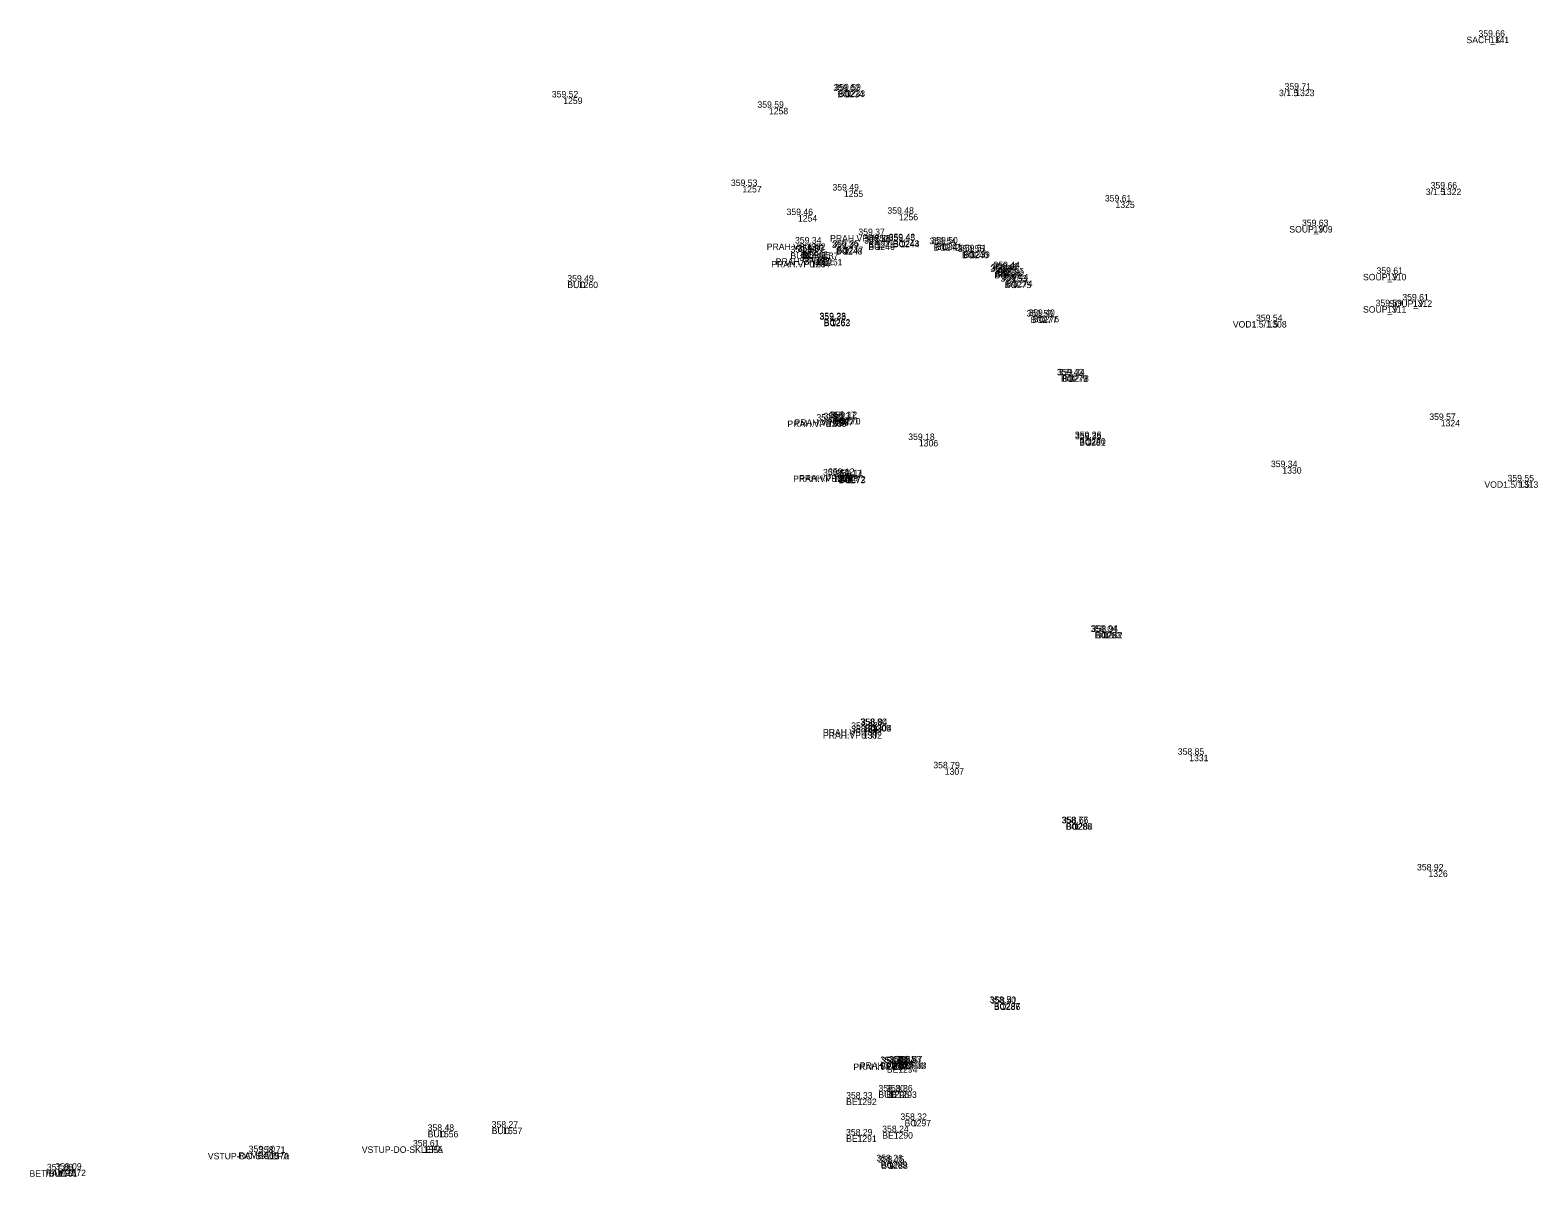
# Model space of a CAD drawing. Extents: x -590413 to -590216, y -1129419 to -1129249.
# Drawn here: x -590376.56 to -590353.25, y -1129285.39 to -1129267.65 of the extents above; entities that cross this region are included whole.
import ezdxf

# ---------------------------------------------------------------- set-up
doc = ezdxf.new("R2010")
doc.units = 0
for name, color, linetype in [('Vrstva B24', 7, 'Continuous'), ('Vrstva B58', 7, 'Continuous'), ('Vrstva B59', 7, 'Continuous'), ('Vrstva B60', 7, 'Continuous')]:
    doc.layers.add(name, color=color, linetype=linetype)

msp = doc.modelspace()

# ---------------------------------------------------------------- linework, layer by layer
at = {"layer": 'Vrstva B60'}
for p, q in [((-590353.99, -1129267.75), (-590353.99, -1129267.75)), ((-590363.97, -1129268.59), (-590363.97, -1129268.59)), ((-590363.95, -1129268.58), (-590363.95, -1129268.58)), ((-590357, -1129268.57), (-590357, -1129268.57)), ((-590368.32, -1129268.69), (-590368.32, -1129268.69)), ((-590365.14, -1129268.85), (-590365.14, -1129268.85)), ((-590365.55, -1129270.06), (-590365.55, -1129270.06)), ((-590363.98, -1129270.13), (-590363.98, -1129270.13)), ((-590359.78, -1129270.3), (-590359.78, -1129270.3)), ((-590354.73, -1129270.1), (-590354.73, -1129270.1)), ((-590364.69, -1129270.51), (-590364.69, -1129270.51)), ((-590363.13, -1129270.49), (-590363.13, -1129270.49)), ((-590356.72, -1129270.68), (-590356.72, -1129270.68)), ((-590364.56, -1129270.95), (-590364.56, -1129270.95)), ((-590363.98, -1129271), (-590363.98, -1129271)), ((-590363.58, -1129270.82), (-590363.58, -1129270.82)), ((-590363.49, -1129270.92), (-590363.49, -1129270.92)), ((-590363.49, -1129270.95), (-590363.49, -1129270.95)), ((-590363.11, -1129270.9), (-590363.11, -1129270.9)), ((-590363.11, -1129270.91), (-590363.11, -1129270.91)), ((-590362.48, -1129270.96), (-590362.48, -1129270.96)), ((-590362.45, -1129270.95), (-590362.45, -1129270.95)), ((-590364.63, -1129271.09), (-590364.63, -1129271.09)), ((-590364.52, -1129271.07), (-590364.52, -1129271.07)), ((-590364.52, -1129271.08), (-590364.52, -1129271.08)), ((-590364.49, -1129271.22), (-590364.49, -1129271.22)), ((-590364.42, -1129271.18), (-590364.42, -1129271.18)), ((-590364.3, -1129271.19), (-590364.3, -1129271.19)), ((-590363.99, -1129271.02), (-590363.99, -1129271.02)), ((-590362.04, -1129271.08), (-590362.04, -1129271.08)), ((-590362.02, -1129271.07), (-590362.02, -1129271.07)), ((-590361.54, -1129271.39), (-590361.54, -1129271.39)), ((-590361.53, -1129271.37), (-590361.53, -1129271.37)), ((-590361.5, -1129271.35), (-590361.5, -1129271.35)), ((-590361.49, -1129271.33), (-590361.49, -1129271.33)), ((-590355.58, -1129271.42), (-590355.58, -1129271.42)), ((-590368.08, -1129271.54), (-590368.08, -1129271.54)), ((-590361.38, -1129271.54), (-590361.38, -1129271.54)), ((-590361.36, -1129271.52), (-590361.36, -1129271.52)), ((-590355.58, -1129271.92), (-590355.58, -1129271.92)), ((-590355.18, -1129271.83), (-590355.18, -1129271.83)), ((-590364.18, -1129272.12), (-590364.18, -1129272.12)), ((-590364.18, -1129272.13), (-590364.18, -1129272.13)), ((-590360.98, -1129272.08), (-590360.98, -1129272.08)), ((-590360.95, -1129272.07), (-590360.95, -1129272.07)), ((-590357.43, -1129272.15), (-590357.43, -1129272.15)), ((-590360.51, -1129272.99), (-590360.51, -1129272.99)), ((-590360.49, -1129272.99), (-590360.49, -1129272.99)), ((-590364.24, -1129273.69), (-590364.24, -1129273.69)), ((-590364.13, -1129273.67), (-590364.13, -1129273.67)), ((-590364.04, -1129273.65), (-590364.04, -1129273.65)), ((-590364.02, -1129273.65), (-590364.02, -1129273.65)), ((-590354.75, -1129273.68), (-590354.75, -1129273.68)), ((-590362.82, -1129273.99), (-590362.82, -1129273.99)), ((-590360.23, -1129273.96), (-590360.23, -1129273.96)), ((-590360.23, -1129273.98), (-590360.23, -1129273.98)), ((-590357.2, -1129274.41), (-590357.2, -1129274.41)), ((-590364.15, -1129274.54), (-590364.15, -1129274.54)), ((-590364.06, -1129274.53), (-590364.06, -1129274.53)), ((-590363.95, -1129274.56), (-590363.95, -1129274.56)), ((-590363.94, -1129274.55), (-590363.94, -1129274.55)), ((-590353.54, -1129274.63), (-590353.54, -1129274.63)), ((-590359.99, -1129276.96), (-590359.99, -1129276.96)), ((-590359.97, -1129276.96), (-590359.97, -1129276.96)), ((-590363.69, -1129278.46), (-590363.69, -1129278.46)), ((-590363.55, -1129278.4), (-590363.55, -1129278.4)), ((-590363.54, -1129278.4), (-590363.54, -1129278.4)), ((-590363.69, -1129278.51), (-590363.69, -1129278.51)), ((-590358.64, -1129278.86), (-590358.64, -1129278.86)), ((-590362.42, -1129279.07), (-590362.42, -1129279.07)), ((-590360.44, -1129279.92), (-590360.44, -1129279.92)), ((-590360.43, -1129279.92), (-590360.43, -1129279.92)), ((-590354.94, -1129280.65), (-590354.94, -1129280.65)), ((-590361.55, -1129282.7), (-590361.55, -1129282.7)), ((-590361.55, -1129282.71), (-590361.55, -1129282.71)), ((-590363.24, -1129283.63), (-590363.24, -1129283.63)), ((-590363.22, -1129283.64), (-590363.22, -1129283.64)), ((-590363.14, -1129283.68), (-590363.14, -1129283.68)), ((-590363.12, -1129283.62), (-590363.12, -1129283.62)), ((-590363.02, -1129283.62), (-590363.02, -1129283.62)), ((-590363, -1129283.62), (-590363, -1129283.62)), ((-590363.77, -1129284.18), (-590363.77, -1129284.18)), ((-590363.27, -1129284.07), (-590363.27, -1129284.07)), ((-590363.15, -1129284.07), (-590363.15, -1129284.07)), ((-590362.93, -1129284.51), (-590362.93, -1129284.51)), ((-590370.24, -1129284.68), (-590370.24, -1129284.68)), ((-590369.25, -1129284.63), (-590369.25, -1129284.63)), ((-590363.77, -1129284.75), (-590363.77, -1129284.75)), ((-590363.21, -1129284.7), (-590363.21, -1129284.7)), ((-590370.48, -1129284.92), (-590370.48, -1129284.92)), ((-590373.02, -1129285.01), (-590373.02, -1129285.01)), ((-590372.86, -1129285.02), (-590372.86, -1129285.02)), ((-590363.3, -1129285.15), (-590363.3, -1129285.15)), ((-590363.29, -1129285.17), (-590363.29, -1129285.17)), ((-590376.13, -1129285.29), (-590376.13, -1129285.29)), ((-590376, -1129285.28), (-590376, -1129285.28))]:
    msp.add_line(p, q, dxfattribs=at)

# ---------------------------------------------------------------- texts
at = {"layer": 'Vrstva B24'}
for s, p in [('SACH_K', (-590354.352, -1129267.85)), ('BO', (-590364.082, -1129268.69)), ('BO', (-590364.062, -1129268.68)), ('3/1.5', (-590357.251, -1129268.67)), ('3/1.5', (-590354.981, -1129270.2)), ('SOUP_V', (-590357.092, -1129270.78)), ('PRAH.VPUST', (-590365.174, -1129271.05)), ('PRAH.VPUST', (-590364.194, -1129270.92)), ('BO', (-590364.092, -1129271.1)), ('BO', (-590363.602, -1129271.02)), ('BO', (-590363.602, -1129271.05)), ('BO', (-590363.222, -1129271)), ('BO', (-590363.222, -1129271.01)), ('BO', (-590362.592, -1129271.06)), ('BO', (-590362.562, -1129271.05)), ('PRAH.VPUST', (-590365.104, -1129271.32)), ('PRAH.VPUST', (-590365.034, -1129271.28)), ('BUD', (-590364.807, -1129271.19)), ('BO', (-590364.632, -1129271.17)), ('BO', (-590364.632, -1129271.18)), ('BO', (-590364.412, -1129271.29)), ('BO', (-590364.102, -1129271.12)), ('BO', (-590362.152, -1129271.18)), ('BO', (-590362.132, -1129271.17)), ('BO', (-590361.652, -1129271.49)), ('BO', (-590361.642, -1129271.47)), ('BO', (-590361.612, -1129271.45)), ('BO', (-590361.602, -1129271.43)), ('SOUP_V', (-590355.952, -1129271.52)), ('BUD', (-590368.257, -1129271.64)), ('BO', (-590361.492, -1129271.64)), ('BO', (-590361.472, -1129271.62)), ('SOUP_V', (-590355.952, -1129272.02)), ('SOUP_V', (-590355.552, -1129271.93)), ('BO', (-590364.292, -1129272.22)), ('BO', (-590364.292, -1129272.23)), ('BO', (-590361.092, -1129272.18)), ('BO', (-590361.062, -1129272.17)), ('VOD1.5/1.5', (-590357.965, -1129272.25)), ('BO', (-590360.622, -1129273.09)), ('BO', (-590360.602, -1129273.09)), ('PRAH.VPUST', (-590364.854, -1129273.79)), ('PRAH.VPUST', (-590364.744, -1129273.77)), ('BO', (-590364.152, -1129273.75)), ('BO', (-590364.132, -1129273.75)), ('BO', (-590360.342, -1129274.06)), ('BO', (-590360.342, -1129274.08)), ('PRAH.VPUST', (-590364.764, -1129274.64)), ('PRAH.VPUST', (-590364.674, -1129274.63)), ('BO', (-590364.062, -1129274.66)), ('BO', (-590364.052, -1129274.65)), ('VOD1.5/1.5', (-590354.075, -1129274.73)), ('BO', (-590360.102, -1129277.06)), ('BO', (-590360.082, -1129277.06)), ('PRAH.VPUST', (-590364.304, -1129278.56)), ('BO', (-590363.662, -1129278.5)), ('BO', (-590363.652, -1129278.5)), ('PRAH.VPUST', (-590364.304, -1129278.61)), ('BO', (-590360.552, -1129280.02)), ('BO', (-590360.542, -1129280.02)), ('BO', (-590361.662, -1129282.8)), ('BO', (-590361.662, -1129282.81)), ('PRAH.VPUST', (-590363.834, -1129283.74)), ('PRAH.VPUST', (-590363.734, -1129283.72)), ('BET', (-590363.416, -1129283.73)), ('BET', (-590363.316, -1129283.78)), ('BO', (-590363.132, -1129283.72)), ('BO', (-590363.112, -1129283.72)), ('BET', (-590363.946, -1129284.28)), ('BUD', (-590363.447, -1129284.17)), ('BET', (-590363.326, -1129284.17)), ('BO', (-590363.042, -1129284.61)), ('BUD', (-590370.417, -1129284.78)), ('BUD', (-590369.427, -1129284.73)), ('BET', (-590363.946, -1129284.85)), ('BET', (-590363.386, -1129284.8)), ('VSTUP-DO-SKLEPA', (-590371.436, -1129285.02)), ('VSTUP-DO-SKLEPA', (-590373.816, -1129285.12)), ('RAMPA', (-590373.343, -1129285.11)), ('BO', (-590363.412, -1129285.25)), ('BO', (-590363.402, -1129285.27)), ('BET/BUD', (-590376.575, -1129285.39)), ('RAMPA', (-590376.323, -1129285.38))]:
    msp.add_text(s, height=0.1, dxfattribs=at).set_placement(p)
at = {"layer": 'Vrstva B58'}
for s, p in [('359.66', (-590354.166, -1129267.75)), ('359.52', (-590368.497, -1129268.69)), ('359.62', (-590364.146, -1129268.59)), ('359.59', (-590364.127, -1129268.58)), ('359.71', (-590357.165, -1129268.57)), ('359.59', (-590365.317, -1129268.85)), ('359.53', (-590365.727, -1129270.06)), ('359.49', (-590364.157, -1129270.13)), ('359.66', (-590354.906, -1129270.1)), ('359.61', (-590359.944, -1129270.3)), ('359.46', (-590364.867, -1129270.51)), ('359.48', (-590363.307, -1129270.49)), ('359.37', (-590363.756, -1129270.82)), ('359.63', (-590356.896, -1129270.68)), ('359.34', (-590364.806, -1129271.09)), ('359.34', (-590364.736, -1129270.95)), ('359.33', (-590364.696, -1129271.07)), ('359.37', (-590364.696, -1129271.08)), ('359.39', (-590364.166, -1129271.02)), ('359.35', (-590364.156, -1129271)), ('359.40', (-590363.667, -1129270.95)), ('359.38', (-590363.666, -1129270.92)), ('359.43', (-590363.287, -1129270.9)), ('359.45', (-590363.287, -1129270.91)), ('359.54', (-590362.657, -1129270.96)), ('359.50', (-590362.627, -1129270.95)), ('359.55', (-590362.217, -1129271.08)), ('359.51', (-590362.185, -1129271.07)), ('359.35', (-590364.666, -1129271.22)), ('359.35', (-590364.596, -1129271.18)), ('359.37', (-590364.476, -1129271.19)), ('359.44', (-590361.667, -1129271.33)), ('359.49', (-590368.257, -1129271.54)), ('359.54', (-590361.717, -1129271.39)), ('359.47', (-590361.707, -1129271.37)), ('359.47', (-590361.677, -1129271.35)), ('359.53', (-590361.557, -1129271.54)), ('359.44', (-590361.537, -1129271.52)), ('359.61', (-590355.744, -1129271.42)), ('359.59', (-590355.757, -1129271.92)), ('359.61', (-590355.344, -1129271.83)), ('359.28', (-590364.357, -1129272.12)), ('359.33', (-590364.356, -1129272.13)), ('359.50', (-590361.157, -1129272.08)), ('359.40', (-590361.127, -1129272.07)), ('359.54', (-590357.607, -1129272.15)), ('359.43', (-590360.687, -1129272.99)), ('359.34', (-590360.666, -1129272.99)), ('359.13', (-590364.295, -1129273.67)), ('359.17', (-590364.205, -1129273.65)), ('359.12', (-590364.185, -1129273.65)), ('359.12', (-590364.405, -1129273.69)), ('359.57', (-590354.927, -1129273.68)), ('359.18', (-590362.985, -1129273.99)), ('359.26', (-590360.407, -1129273.96)), ('359.35', (-590360.406, -1129273.98)), ('359.11', (-590364.303, -1129274.54)), ('359.12', (-590364.225, -1129274.53)), ('359.17', (-590364.115, -1129274.56)), ('359.11', (-590364.093, -1129274.55)), ('359.34', (-590357.376, -1129274.41)), ('359.55', (-590353.717, -1129274.63)), ('359.04', (-590360.167, -1129276.96)), ('358.94', (-590360.147, -1129276.96)), ('358.87', (-590363.867, -1129278.46)), ('358.88', (-590363.867, -1129278.51)), ('358.90', (-590363.727, -1129278.4)), ('358.84', (-590363.717, -1129278.4)), ('358.85', (-590358.817, -1129278.86)), ('358.79', (-590362.597, -1129279.07)), ('358.77', (-590360.617, -1129279.92)), ('358.66', (-590360.606, -1129279.92)), ('358.92', (-590355.117, -1129280.65)), ('358.50', (-590361.727, -1129282.7)), ('358.41', (-590361.715, -1129282.71)), ('358.53', (-590363.417, -1129283.63)), ('358.52', (-590363.397, -1129283.64)), ('358.44', (-590363.317, -1129283.68)), ('358.51', (-590363.285, -1129283.62)), ('358.53', (-590363.197, -1129283.62)), ('358.47', (-590363.177, -1129283.62)), ('358.30', (-590363.446, -1129284.07)), ('358.36', (-590363.326, -1129284.07)), ('358.33', (-590363.946, -1129284.18)), ('358.32', (-590363.106, -1129284.51)), ('358.48', (-590370.417, -1129284.68)), ('358.27', (-590369.427, -1129284.63)), ('358.29', (-590363.947, -1129284.75)), ('358.24', (-590363.387, -1129284.7)), ('359.10', (-590373.185, -1129285.01)), ('358.71', (-590373.025, -1129285.02)), ('358.61', (-590370.644, -1129284.92)), ('357.88', (-590376.307, -1129285.29)), ('359.09', (-590376.177, -1129285.28)), ('358.26', (-590363.477, -1129285.15)), ('358.15', (-590363.455, -1129285.17))]:
    msp.add_text(s, height=0.1, dxfattribs=at).set_placement(p)
at = {"layer": 'Vrstva B59'}
for s, p in [('1141', (-590353.99, -1129267.85)), ('1234', (-590363.97, -1129268.69)), ('1233', (-590363.95, -1129268.68)), ('1323', (-590357, -1129268.67)), ('1259', (-590368.32, -1129268.79)), ('1258', (-590365.14, -1129268.95)), ('1257', (-590365.55, -1129270.16)), ('1255', (-590363.98, -1129270.23)), ('1325', (-590359.78, -1129270.4)), ('1322', (-590354.73, -1129270.2)), ('1254', (-590364.69, -1129270.61)), ('1256', (-590363.13, -1129270.59)), ('1309', (-590356.72, -1129270.78)), ('1252', (-590364.56, -1129271.05)), ('1247', (-590363.98, -1129271.1)), ('1253', (-590363.58, -1129270.92)), ('1245', (-590363.49, -1129271.02)), ('1246', (-590363.49, -1129271.05)), ('1243', (-590363.11, -1129271)), ('1244', (-590363.11, -1129271.01)), ('1242', (-590362.48, -1129271.06)), ('1241', (-590362.45, -1129271.05)), ('1251', (-590364.63, -1129271.19)), ('1249', (-590364.52, -1129271.17)), ('1250', (-590364.52, -1129271.18)), ('1264', (-590364.49, -1129271.32)), ('1265', (-590364.42, -1129271.28)), ('1261', (-590364.3, -1129271.29)), ('1248', (-590363.99, -1129271.12)), ('1240', (-590362.04, -1129271.18)), ('1239', (-590362.02, -1129271.17)), ('1238', (-590361.54, -1129271.49)), ('1237', (-590361.53, -1129271.47)), ('1236', (-590361.5, -1129271.45)), ('1235', (-590361.49, -1129271.43)), ('1310', (-590355.58, -1129271.52)), ('1260', (-590368.08, -1129271.64)), ('1275', (-590361.38, -1129271.64)), ('1274', (-590361.36, -1129271.62)), ('1311', (-590355.58, -1129272.02)), ('1312', (-590355.18, -1129271.93)), ('1262', (-590364.18, -1129272.22)), ('1263', (-590364.18, -1129272.23)), ('1277', (-590360.98, -1129272.18)), ('1276', (-590360.95, -1129272.17)), ('1308', (-590357.43, -1129272.25)), ('1279', (-590360.51, -1129273.09)), ('1278', (-590360.49, -1129273.09)), ('1266', (-590364.24, -1129273.79)), ('1267', (-590364.13, -1129273.77)), ('1271', (-590364.04, -1129273.75)), ('1270', (-590364.02, -1129273.75)), ('1324', (-590354.75, -1129273.78)), ('1306', (-590362.82, -1129274.09)), ('1280', (-590360.23, -1129274.06)), ('1281', (-590360.23, -1129274.08)), ('1330', (-590357.2, -1129274.51)), ('1268', (-590364.15, -1129274.64)), ('1269', (-590364.06, -1129274.63)), ('1273', (-590363.95, -1129274.66)), ('1272', (-590363.94, -1129274.65)), ('1313', (-590353.54, -1129274.73)), ('1283', (-590359.99, -1129277.06)), ('1282', (-590359.97, -1129277.06)), ('1303', (-590363.69, -1129278.56)), ('1305', (-590363.55, -1129278.5)), ('1304', (-590363.54, -1129278.5)), ('1302', (-590363.69, -1129278.61)), ('1331', (-590358.64, -1129278.96)), ('1307', (-590362.42, -1129279.17)), ('1285', (-590360.44, -1129280.02)), ('1284', (-590360.43, -1129280.02)), ('1326', (-590354.94, -1129280.75)), ('1287', (-590361.55, -1129282.8)), ('1286', (-590361.55, -1129282.81)), ('1295', (-590363.24, -1129283.73)), ('1301', (-590363.22, -1129283.74)), ('1294', (-590363.14, -1129283.78)), ('1300', (-590363.12, -1129283.72)), ('1299', (-590363.02, -1129283.72)), ('1298', (-590363, -1129283.72)), ('1292', (-590363.77, -1129284.28)), ('1296', (-590363.27, -1129284.17)), ('1293', (-590363.15, -1129284.17)), ('1297', (-590362.93, -1129284.61)), ('1556', (-590370.24, -1129284.78)), ('1557', (-590369.25, -1129284.73)), ('1291', (-590363.77, -1129284.85)), ('1290', (-590363.21, -1129284.8)), ('1555', (-590370.48, -1129285.02)), ('1569', (-590373.02, -1129285.11)), ('1570', (-590372.86, -1129285.12)), ('1289', (-590363.3, -1129285.25)), ('1288', (-590363.29, -1129285.27)), ('1561', (-590376.13, -1129285.39)), ('1572', (-590376, -1129285.38))]:
    msp.add_text(s, height=0.1, dxfattribs=at).set_placement(p)

doc.saveas('drawing.dxf')
